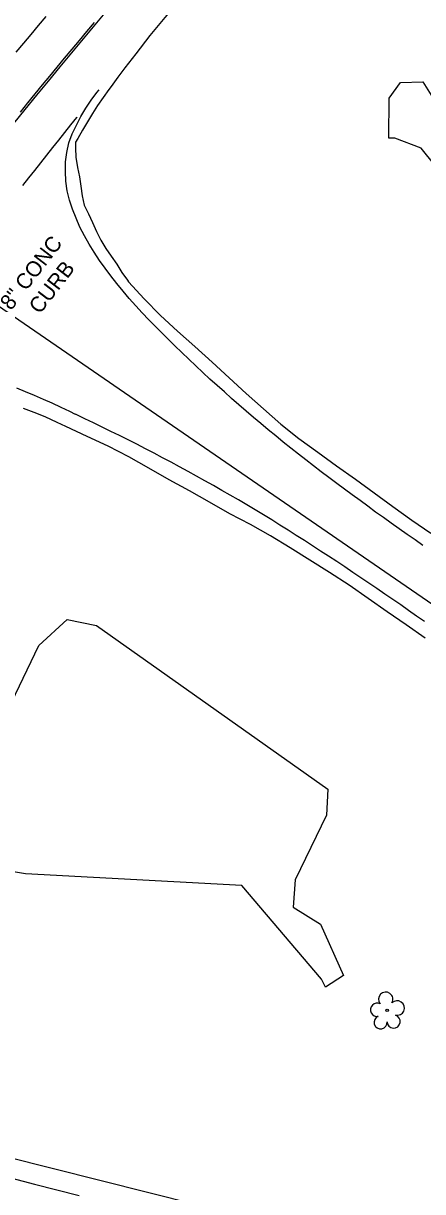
# Model space of a CAD drawing. Extents: x 1182322 to 1186765, y 572295 to 575411.
# Drawn here: x 1184747.4 to 1184850.6, y 574067.7 to 574370 of the extents above; entities that cross this region are included whole.
import ezdxf

# ---------------------------------------------------------------- set-up
doc = ezdxf.new("R2010")
doc.units = 0
for name, color, linetype in [('COGO Default Chain', 7, 'Continuous'), ('Exist Guardrail', 7, 'Continuous'), ('Exist Horizontal Alignment', 7, 'Continuous'), ('Exist Roads Curbs Text', 7, 'Continuous'), ('Exist Roads EOP', 7, 'Continuous'), ('Exist Roads EOT', 7, 'Continuous'), ('Exist Vegetation Tree CELL', 7, 'Continuous'), ('Exist Vegetation Woods Line', 7, 'Continuous')]:
    doc.layers.add(name, color=color, linetype=linetype)

msp = doc.modelspace()

# ---------------------------------------------------------------- linework, layer by layer
at = {"layer": 'COGO Default Chain'}
msp.add_line((1184719.29, 574311.8), (1184941.07, 574159.14), dxfattribs=at)
msp.add_arc((1186339.97, 573055.26), 2050.73, 139.87385, 144.10304, dxfattribs=at)
at = {"layer": 'Exist Guardrail'}
msp.add_lwpolyline([(1184664.96, 574096.62), (1184686.03, 574091.19), (1184742.82, 574076.79), (1184791.79, 574064.46), (1184819.91, 574057.89)], dxfattribs=at)
at = {"layer": 'Exist Horizontal Alignment'}
msp.add_line((1184719.29, 574311.8), (1184941.07, 574159.14), dxfattribs=at)
msp.add_arc((1186339.97, 573055.26), 2050.73, 139.87385, 144.10304, dxfattribs=at)
at = {"layer": 'Exist Roads EOP'}
for points in [[(1184840.48, 574433.51), (1184836.22, 574429.25), (1184831.98, 574425.07), (1184827.75, 574420.82), (1184823.58, 574416.5), (1184819.47, 574412.13), (1184815.36, 574407.75), (1184811.36, 574403.29), (1184807.39, 574398.79), (1184803.42, 574394.29), (1184799.45, 574389.79), (1184795.52, 574385.25), (1184791.59, 574380.72), (1184787.74, 574376.12), (1184783.92, 574371.5), (1184780.09, 574366.87), (1184776.42, 574362.12), (1184775.49, 574360.91)], [(1184775.46, 574360.87), (1184773.64, 574358.48), (1184771.83, 574356.09), (1184770.04, 574353.68), (1184769.46, 574352.87)], [(1184769.44, 574352.85), (1184768, 574350.84), (1184766.58, 574348.78), (1184765.22, 574346.68), (1184763.94, 574344.54), (1184762.69, 574342.38), (1184761.45, 574340.22), (1184760.84, 574339.23), (1184760.86, 574337.73), (1184760.95, 574335.4), (1184761.34, 574332.71), (1184761.86, 574330.3), (1184762.21, 574327.84), (1184762.61, 574325.41), (1184763.09, 574322.93), (1184764.19, 574320.69), (1184765.26, 574318.44), (1184766.32, 574316.18), (1184767.41, 574313.93), (1184768.67, 574311.77), (1184770.11, 574309.73), (1184771.51, 574307.67), (1184772.81, 574305.53), (1184774.27, 574303.51), (1184774.57, 574303.14)], [(1184774.58, 574303.13), (1184778.59, 574298.68), (1184782.8, 574294.41), (1184787.2, 574290.34), (1184791.69, 574286.37), (1184796.14, 574282.36), (1184800.56, 574278.31), (1184804.97, 574274.25), (1184809.45, 574270.27), (1184813.95, 574266.31), (1184818.61, 574262.55), (1184823.48, 574259.04), (1184828.34, 574255.54), (1184833.2, 574252.03), (1184838.04, 574248.5), (1184842.89, 574244.97), (1184847.75, 574241.47), (1184852.69, 574238.08)], [(1184851.2, 574210.89), (1184846.29, 574214.32), (1184841.38, 574217.76), (1184836.47, 574221.2), (1184831.55, 574224.62), (1184826.5, 574227.86), (1184821.43, 574231.05), (1184816.35, 574234.24), (1184811.28, 574237.43), (1184806.04, 574240.35), (1184800.71, 574243.09), (1184795.52, 574246.09), (1184790.28, 574249.01), (1184785.03, 574251.91), (1184779.82, 574254.87), (1184774.62, 574257.85), (1184769.3, 574260.61), (1184763.84, 574263.06), (1184758.4, 574265.71), (1184756.12, 574266.75), (1184752.99, 574268.16), (1184750.16, 574269.27), (1184747.4, 574270.35)], [(1184744.4, 574071.14), (1184750.22, 574069.65), (1184756.03, 574068.16), (1184761.84, 574066.66)]]:
    msp.add_lwpolyline(points, dxfattribs=at)
at = {"layer": 'Exist Roads EOT'}
for points in [[(1184745.56, 574362.53), (1184747.47, 574364.85), (1184749.4, 574367.15), (1184751.32, 574369.45), (1184753.25, 574371.75)], [(1184765.65, 574370.2), (1184763.73, 574367.9), (1184761.81, 574365.59), (1184759.89, 574363.29), (1184757.97, 574360.98), (1184756.05, 574358.68), (1184754.13, 574356.37), (1184752.21, 574354.07), (1184750.31, 574351.75), (1184748.44, 574349.41), (1184746.56, 574347.06)], [(1184783.33, 574289.75), (1184781.57, 574291.53), (1184779.82, 574293.31), (1184778.11, 574295.13), (1184776.41, 574296.95), (1184774.76, 574298.83), (1184773.15, 574300.74), (1184771.56, 574302.67), (1184770.02, 574304.63), (1184768.53, 574306.64), (1184767.1, 574308.68), (1184765.72, 574310.77), (1184764.42, 574312.9), (1184763.17, 574315.06), (1184762.01, 574317.27), (1184760.99, 574319.55), (1184760.1, 574321.89), (1184759.31, 574324.25), (1184758.74, 574326.69), (1184758.37, 574329.16), (1184758.24, 574331.65), (1184758.26, 574334.15), (1184758.58, 574336.62), (1184759.14, 574339.06), (1184760, 574341.4), (1184761.08, 574343.66), (1184762.24, 574345.87), (1184763.52, 574348.02), (1184764.92, 574350.09), (1184766.4, 574352.11), (1184766.97, 574352.84)], [(1184747.22, 574328.07), (1184748.78, 574330.02), (1184750.34, 574331.97), (1184751.9, 574333.93), (1184753.46, 574335.89), (1184755.01, 574337.85), (1184756.56, 574339.81), (1184758.11, 574341.77), (1184759.67, 574343.72), (1184761.22, 574345.68), (1184761.25, 574345.72)], [(1184850.63, 574234.88), (1184848.59, 574236.32), (1184846.54, 574237.75), (1184844.5, 574239.19), (1184842.46, 574240.63), (1184840.43, 574242.09), (1184838.41, 574243.55), (1184836.39, 574245.03), (1184834.38, 574246.51), (1184832.37, 574247.99), (1184830.37, 574249.48), (1184828.36, 574250.96), (1184826.36, 574252.46), (1184824.37, 574253.97), (1184822.38, 574255.48), (1184820.41, 574257.02), (1184818.44, 574258.55), (1184816.48, 574260.1), (1184814.53, 574261.66), (1184812.6, 574263.24), (1184810.68, 574264.83), (1184808.76, 574266.44), (1184806.86, 574268.05), (1184804.95, 574269.67), (1184803.07, 574271.31), (1184801.19, 574272.95), (1184799.32, 574274.61), (1184797.47, 574276.28), (1184795.61, 574277.96), (1184793.79, 574279.66), (1184791.96, 574281.37), (1184790.14, 574283.08), (1184788.33, 574284.79), (1184786.53, 574286.52), (1184784.77, 574288.29), (1184783.34, 574289.74)], [(1184745.57, 574275.69), (1184747.88, 574274.74), (1184750.18, 574273.76), (1184752.48, 574272.77), (1184754.76, 574271.77), (1184757.03, 574270.71), (1184759.28, 574269.63), (1184760.73, 574268.91)], [(1184851.04, 574215.21), (1184848.99, 574216.64), (1184846.94, 574218.06), (1184844.89, 574219.49), (1184842.84, 574220.91), (1184840.78, 574222.32), (1184838.72, 574223.73), (1184836.66, 574225.15), (1184834.59, 574226.54), (1184832.51, 574227.93), (1184830.44, 574229.33), (1184828.37, 574230.72), (1184826.27, 574232.09), (1184824.18, 574233.45), (1184822.09, 574234.81), (1184820, 574236.18), (1184817.88, 574237.51), (1184815.77, 574238.84), (1184813.66, 574240.18), (1184811.55, 574241.51), (1184809.41, 574242.81), (1184807.28, 574244.11), (1184805.14, 574245.4), (1184803.01, 574246.7), (1184800.84, 574247.93), (1184798.66, 574249.15), (1184796.48, 574250.38), (1184794.3, 574251.6), (1184792.12, 574252.82), (1184789.93, 574254.02), (1184787.75, 574255.23), (1184785.56, 574256.44), (1184783.35, 574257.61), (1184781.15, 574258.78), (1184778.94, 574259.94), (1184776.73, 574261.11), (1184774.49, 574262.22), (1184772.25, 574263.32), (1184770.01, 574264.43), (1184767.77, 574265.53), (1184765.52, 574266.61), (1184763.27, 574267.69), (1184761.02, 574268.77), (1184760.74, 574268.9)]]:
    msp.add_lwpolyline(points, dxfattribs=at)
at = {"layer": 'Exist Vegetation Tree CELL'}
msp.add_line((1184841.4, 574114.6), (1184841.4, 574114.6), dxfattribs=at)
msp.add_circle((1184841.4, 574114.6), 0.326, dxfattribs=at)
for centre, radius, start, end in [((1184841.01, 574117.47), 1.86, 330.1651, 219.7134), ((1184838.79, 574114.75), 1.73, 62.6636, 279.3457), ((1184843.95, 574115.19), 1.9, 257.1011, 134.1999), ((1184839.69, 574111.48), 1.69, 111.5671, 6.231), ((1184843.07, 574111.7), 1.7, 181.2822, 74.56)]:
    msp.add_arc(centre, radius, start, end, dxfattribs=at)
at = {"layer": 'Exist Vegetation Woods Line'}
for points in [[(1184956.49, 574241.28), (1184948.61, 574251.61), (1184944.9, 574254.04), (1184926.51, 574260.39), (1184913.34, 574272.76), (1184868.17, 574315.29), (1184850.16, 574337.71), (1184843.38, 574340.29), (1184841.79, 574340.29), (1184841.92, 574350.63), (1184844.82, 574354.69), (1184850.62, 574354.85), (1184857.48, 574343.82), (1184859.28, 574340.94), (1184873.23, 574336.64), (1184881.84, 574338.2), (1184883.81, 574334.29), (1184879.43, 574311.99), (1184944.53, 574273.83), (1184949.68, 574274.69), (1184966.63, 574274.59), (1184967.6, 574272.76), (1184971.1, 574260.9)], [(1184728.15, 574160.65), (1184751.37, 574208.97), (1184758.71, 574215.75), (1184766.24, 574214.22), (1184826.07, 574171.87), (1184825.74, 574165.07), (1184817.66, 574148.38), (1184817.12, 574141.27), (1184824.2, 574136.89), (1184830.12, 574123.58), (1184825.46, 574120.56), (1184824.45, 574122.64), (1184803.88, 574146.89), (1184747.93, 574149.91), (1184743.3, 574150.73), (1184733.21, 574157.26), (1184728.15, 574160.65)]]:
    msp.add_lwpolyline(points, dxfattribs=at)

# ---------------------------------------------------------------- texts
at = {"layer": 'Exist Roads Curbs Text'}
for s, p in [('8" CONC', (1184744.19, 574295.52)), ('CURB', (1184751.64, 574294.55))]:
    msp.add_text(s, height=4, rotation=52.4023, dxfattribs=at).set_placement(p)

doc.saveas('drawing.dxf')
